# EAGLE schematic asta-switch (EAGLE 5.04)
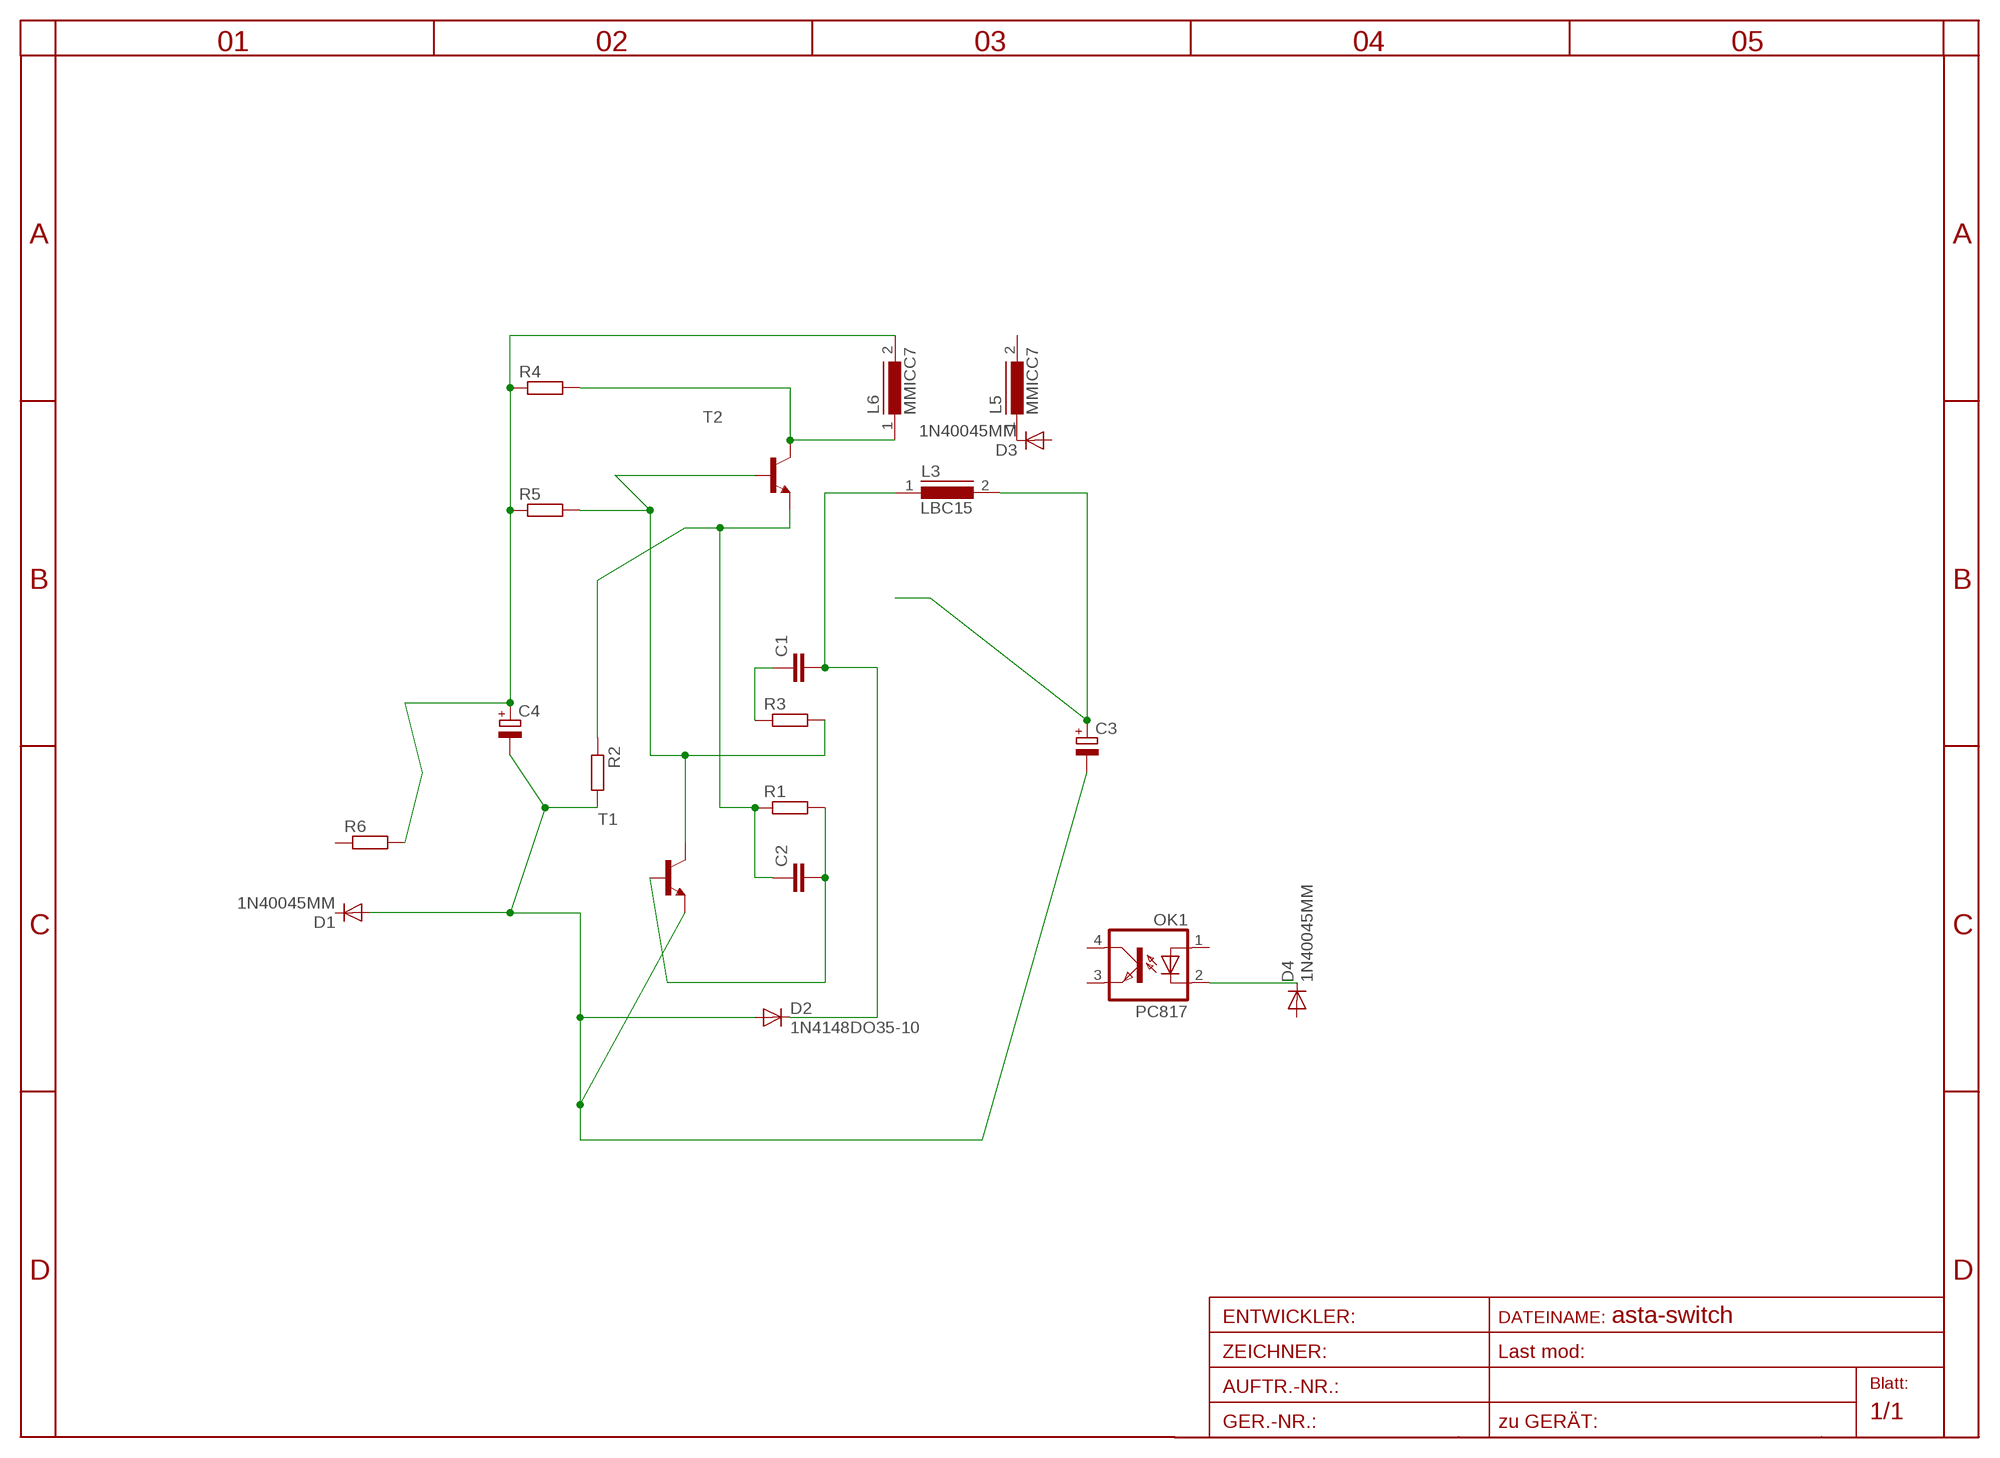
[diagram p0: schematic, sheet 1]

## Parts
C1  C-EU025-024X044  [C025-024X044]
C2  C-EU025-024X044  [C025-024X044]
C3  CPOL-EUE2,5-6E  [E2,5-6E]
C4  CPOL-EUE2,5-6E  [E2,5-6E]
D1  1N40045MM  [C1702-05]
D2  1N4148DO35-10  [DO35-10]
D3  1N40045MM  [C1702-05]
D4  1N40045MM  [C1702-05]
L3  LBC15  [LBC15]
L5  MMICC7  [MMICC7]
L6  MMICC7  [MMICC7]
OK1  PC817  [DIL04]
R1  R-EU_0204/5  [0204/5]
R2  R-EU_0207/12  [0207/12]
R3  R-EU_0204/5  [0204/5]
R4  R-EU_0204/7  [0204/7]
R5  R-EU_0204/5  [0204/5]
R6  R-EU_0204/5  [0204/5]
T1  -NPN-TO92-ECB  [TO92-ECB]
T2  -NPN-TO92-ECB  [TO92-ECB]

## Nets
N$1: C3.- C4.- D1.A D2.A R2.2 T1.E
N$2: C4.+ L6.2 R4.1 R5.1 R6.2
N$3: L6.1 R4.2 T2.C
N$4: R3.2 R5.2 T1.C T2.B
N$5: C1.2 D2.C L3.1
N$6: C1.1 R3.1
N$7: C2.1 R1.1 R2.1 T2.E
N$8: C2.2 R1.2 T1.B
N$9: C3.+ L3.2
N$10: D3.C L5.1
N$11: D4.C OK1.2(C)
Unconnected: D1.C D3.A D4.A L5.2 OK1.1(A) OK1.3(EMIT) OK1.4(COL) R6.1

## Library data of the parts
C1 C2 = rcl:C-EU: CAPACITOR, European symbol
C3 C4 = rcl:CPOL-EU: POLARIZED CAPACITOR, European symbol
D1 D3 D4 = diode-1:1N4004: DIODE
D2 = diode-1:1N4148: DIODE
L3 = inductors:LBC15: INDUCTOR
L5 L6 = inductors:MMICC7: INDUCTOR
OK1 = optocoupler:PC817: SHARP OPTO COUPLER
R1-R6 = rcl:R-EU_: RESISTOR, European symbol
T1 T2 = transistor:*-NPN-: NPN Transistror BF959 corrected 2008.03.06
